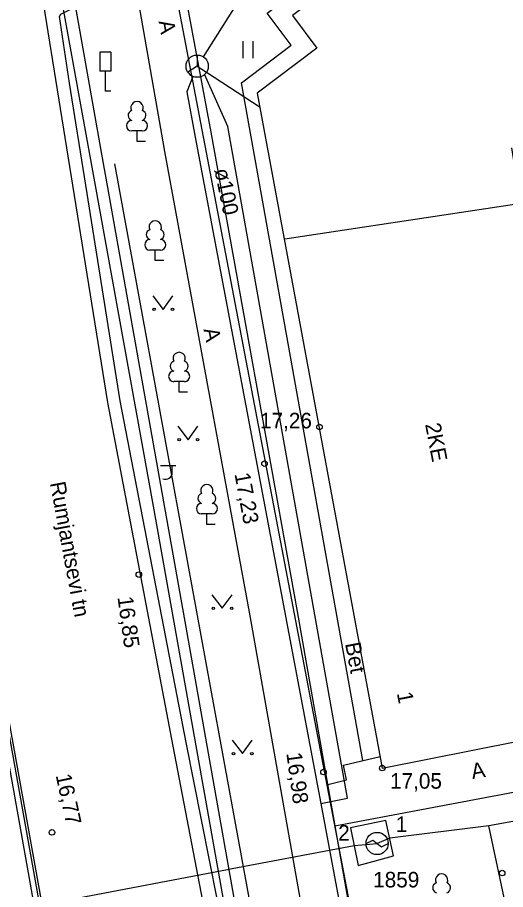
# Model space of a CAD drawing. Extents: x 713540 to 713867, y 6589774 to 6590061.
# Drawn here: x 713700.77 to 713722.79, y 6589841.34 to 6589880.65 of the extents above; entities that cross this region are included whole.
import ezdxf

# ---------------------------------------------------------------- set-up
doc = ezdxf.new("R2010")
doc.units = 0
for name, color, linetype in [('HALJASTUS', 7, 'Continuous'), ('HOONE', 7, 'Continuous'), ('HOONEDET', 7, 'Continuous'), ('KAEVU_NR', 7, 'Continuous'), ('KORGUS', 7, 'Continuous'), ('KPKAABEL', 7, 'Continuous'), ('LIIKLUS', 7, 'Continuous'), ('MPKAABEL', 7, 'Continuous'), ('PUU', 7, 'Continuous'), ('SIKAEV', 7, 'Continuous'), ('SITRASS', 7, 'Continuous'), ('TEE', 7, 'Continuous'), ('TORU NR', 7, 'Continuous'), ('По умолчанию', 7, 'Continuous'), ('Слой 1', 7, 'Continuous')]:
    doc.layers.add(name, color=color, linetype=linetype)

msp = doc.modelspace()

# ---------------------------------------------------------------- linework, layer by layer
at = {"layer": 'HALJASTUS'}
for p, q in [((713710.943, 6589879.583), (713710.943, 6589878.822)), ((713711.398, 6589879.583), (713711.398, 6589878.822)), ((713706.877, 6589868.097), (713707.34, 6589867.49)), ((713707.34, 6589867.49), (713707.786, 6589868.097)), ((713708.007, 6589862.227), (713708.47, 6589861.62)), ((713708.47, 6589861.62), (713708.916, 6589862.227)), ((713709.547, 6589854.627), (713710.01, 6589854.02)), ((713710.01, 6589854.02), (713710.456, 6589854.627)), ((713710.457, 6589848.077), (713710.92, 6589847.47)), ((713710.92, 6589847.47), (713711.366, 6589848.077))]:
    msp.add_line(p, q, dxfattribs=at)
msp.add_lwpolyline([(713705.159, 6589874.056), (713715.01, 6589820.21)], dxfattribs=at)
for centre, radius in [((713706.939, 6589867.49), 0.055), ((713707.768, 6589867.49), 0.055), ((713708.069, 6589861.62), 0.055), ((713708.898, 6589861.62), 0.055), ((713709.609, 6589854.02), 0.055), ((713710.438, 6589854.02), 0.055), ((713710.519, 6589847.47), 0.055), ((713711.348, 6589847.47), 0.055), ((713722.64, 6589842.085), 0.125)]:
    msp.add_circle(centre, radius, dxfattribs=at)
at = {"layer": 'HOONE'}
for p, q in [((713716.5, 6589843.42), (713716.8, 6589843.57)), ((713716.8, 6589843.57), (713717.2, 6589843.27)), ((713717.2, 6589843.27), (713717.5, 6589843.42))]:
    msp.add_line(p, q, dxfattribs=at)
for points in [[(713724.32, 6589875.59), (713727.08, 6589877.37), (713750.432, 6589865.811), (713755.151, 6589875.615), (713727.26, 6589889.056), (713724.566, 6589887.026), (713723.449, 6589888.508), (713713.179, 6589880.732), (713714.278, 6589879.273), (713711.586, 6589877.244), (713717.23, 6589846.82), (713727.46, 6589848.84), (713724.86, 6589863.5), (713723.07, 6589874.77)], [(713723.5, 6589872.27), (713712.84, 6589870.65)], [(713725.69, 6589844.87), (713722.04, 6589844.22)], [(713715.8, 6589844.12), (713716.15, 6589842.43), (713717.74, 6589842.87), (713717.39, 6589844.45), (713715.8, 6589844.12)], [(713722.04, 6589844.22), (713717.57, 6589843.66), (713717, 6589843.42)], [(713723.69, 6589836.46), (713722.04, 6589844.22)], [(713671.44, 6589834.87), (713687.15, 6589837.855), (713710.253, 6589842.245), (713710.463, 6589842.286), (713715.96, 6589843.33), (713717, 6589843.42)]]:
    msp.add_lwpolyline(points, dxfattribs=at)
msp.add_circle((713717, 6589843.42), 0.5, dxfattribs=at)
at = {"layer": 'HOONEDET'}
msp.add_lwpolyline([(713716.35, 6589847.16), (713710.876, 6589877.709), (713713.129, 6589879.407), (713712.044, 6589880.847), (713723.695, 6589889.578), (713724.782, 6589888.135), (713727.19, 6589889.95), (713755.786, 6589876.063), (713755.151, 6589875.615)], dxfattribs=at)
at = {"layer": 'KORGUS'}
for centre in [(713714.4, 6589862.19), (713711.92, 6589860.54), (713706.25, 6589855.54), (713714.58, 6589846.64), (713717.23, 6589846.82), (713702.33, 6589843.92)]:
    msp.add_circle(centre, 0.125, dxfattribs=at)
at = {"layer": 'KPKAABEL'}
for points in [[(713710.127, 6589839.185), (713708.399, 6589847.895), (713705.413, 6589863.377), (713703.858, 6589873.093), (713703.123, 6589877.685), (713702.671, 6589880.689), (713702.728, 6589880.803), (713706.087, 6589882.482), (713718.389, 6589891.098), (713722.849, 6589893.649), (713723.072, 6589893.73), (713723.275, 6589893.729), (713732.506, 6589888.949), (713748.351, 6589881.095), (713756.711, 6589877.059), (713763.861, 6589873.277), (713777.241, 6589866.985), (713783.126, 6589864.152), (713798.55, 6589856.631), (713806.554, 6589853.297)], [(713700.447, 6589886.145), (713701.061, 6589885.962), (713701.248, 6589885.623), (713703.334, 6589872.63), (713704.833, 6589863.294), (713707.784, 6589847.812), (713713.528, 6589817.88), (713715.336, 6589806.351), (713717.846, 6589793.663), (713718.024, 6589793.474), (713722.293, 6589793.794), (713723.951, 6589793.699), (713735.68, 6589793.289), (713735.884, 6589793.19), (713735.895, 6589792.126)]]:
    msp.add_lwpolyline(points, dxfattribs=at)
at = {"layer": 'LIIKLUS'}
for points in [[(713704.488, 6589879.085), (713704.488, 6589878.235)], [(713704.988, 6589879.085), (713704.488, 6589879.085)], [(713704.988, 6589879.085), (713704.988, 6589878.235)], [(713704.988, 6589878.235), (713704.488, 6589878.235)], [(713704.738, 6589878.235), (713704.738, 6589877.335)], [(713704.988, 6589877.335), (713704.738, 6589877.335)]]:
    msp.add_lwpolyline(points, dxfattribs=at)
at = {"layer": 'MPKAABEL'}
for points in [[(713694.011, 6589938.961), (713692.89, 6589933.64), (713698.13, 6589925.84), (713701.56, 6589922.83), (713707.37, 6589919), (713707.983, 6589913.318), (713708.27, 6589910.66), (713700.37, 6589905.55), (713699.23, 6589901.46), (713701.24, 6589889.8), (713704.212, 6589873.404), (713706.92, 6589858.46), (713712.25, 6589828.58), (713717.93, 6589797.45), (713721.28, 6589780.69), (713722.515, 6589774.068)], [(713733.391, 6589792.128), (713732.429, 6589795.958), (713729.329, 6589801.34), (713725.485, 6589806.569), (713715.308, 6589813.781), (713706.433, 6589812.173), (713706.056, 6589818.501), (713702.321, 6589837.617), (713696.514, 6589869.947), (713694.084, 6589874.558), (713687.448, 6589873.302), (713670.227, 6589869.773), (713666.658, 6589869.039)]]:
    msp.add_lwpolyline(points, dxfattribs=at)
at = {"layer": 'PUU'}
for p, q in [((713706.407, 6589875.535), (713705.927, 6589875.535)), ((713706.167, 6589875.06), (713706.167, 6589875.535)), ((713706.547, 6589875.06), (713706.167, 6589875.06)), ((713707.23, 6589870.165), (713706.75, 6589870.165)), ((713706.99, 6589869.69), (713706.99, 6589870.165)), ((713707.37, 6589869.69), (713706.99, 6589869.69)), ((713708.31, 6589864.235), (713707.83, 6589864.235)), ((713708.07, 6589863.76), (713708.07, 6589864.235)), ((713708.45, 6589863.76), (713708.07, 6589863.76)), ((713709.56, 6589858.275), (713709.08, 6589858.275)), ((713709.32, 6589857.8), (713709.32, 6589858.275)), ((713709.7, 6589857.8), (713709.32, 6589857.8))]:
    msp.add_line(p, q, dxfattribs=at)
for centre, radius, start, end in [((713706.167, 6589876.58), 0.277, 332.5799, 207.4201), ((713705.997, 6589876.232), 0.233, 109.0217, 253.1415), ((713706.337, 6589876.232), 0.233, 286.8508, 70.9859), ((713705.929, 6589875.772), 0.238, 90.0016, 269.3953), ((713706.404, 6589875.772), 0.238, 270.6047, 89.9984), ((713706.99, 6589871.21), 0.277, 332.5799, 207.4201), ((713706.82, 6589870.863), 0.233, 109.0217, 253.1415), ((713707.16, 6589870.863), 0.233, 286.8508, 70.9859), ((713706.753, 6589870.402), 0.238, 90.0016, 269.3953), ((713707.227, 6589870.402), 0.238, 270.6047, 89.9984), ((713708.07, 6589865.28), 0.277, 332.5799, 207.4201), ((713707.9, 6589864.933), 0.233, 109.0217, 253.1415), ((713708.24, 6589864.933), 0.233, 286.8508, 70.9859), ((713707.833, 6589864.472), 0.238, 90.0016, 269.3953), ((713708.307, 6589864.472), 0.238, 270.6047, 89.9984), ((713709.32, 6589859.32), 0.277, 332.5799, 207.4201), ((713709.15, 6589858.973), 0.233, 109.0217, 253.1415), ((713709.49, 6589858.973), 0.233, 286.8508, 70.9859), ((713709.083, 6589858.512), 0.238, 90.0016, 269.3953), ((713709.557, 6589858.512), 0.238, 270.6047, 89.9984), ((713719.91, 6589841.77), 0.277, 332.5799, 207.4201), ((713719.74, 6589841.423), 0.233, 109.0217, 253.1415), ((713720.08, 6589841.423), 0.233, 286.8508, 70.9859)]:
    msp.add_arc(centre, radius, start, end, dxfattribs=at)
at = {"layer": 'SIKAEV'}
for p, q in [((713708.882, 6589878.956), (713708.882, 6589878.456)), ((713708.882, 6589878.456), (713708.467, 6589878.181)), ((713708.882, 6589878.456), (713709.297, 6589878.181))]:
    msp.add_line(p, q, dxfattribs=at)
msp.add_circle((713708.882, 6589878.456), 0.5, dxfattribs=at)
at = {"layer": 'SITRASS'}
for points in [[(713722.087, 6589899.329), (713709.149, 6589878.879)], [(713714.46, 6589845.22), (713715.66, 6589845.46), (713710.263, 6589875.729), (713709.212, 6589878.088)], [(713709.301, 6589878.184), (713711.716, 6589876.611)], [(713708.693, 6589877.993), (713708.41, 6589877.3), (713708.797, 6589875.248), (713714.46, 6589845.22), (713715.85, 6589837.81), (713719.1, 6589820.87), (713720.22, 6589816.17)], [(713615.75, 6589870.91), (713621.3, 6589860.3), (713625.233, 6589860.869), (713625.227, 6589860.885), (713640.96, 6589863.23), (713652.708, 6589865.606), (713653.172, 6589865.67), (713666.653, 6589868.422), (713666.793, 6589868.454), (713693.51, 6589873.89), (713696.19, 6589872.18), (713705.63, 6589819.79), (713706.98, 6589814.25), (713714.585, 6589815.353), (713715.248, 6589815.449), (713720.22, 6589816.17), (713721.73, 6589808.13), (713722.95, 6589800.79), (713723.002, 6589800.484), (713723.148, 6589799.687), (713725.92, 6589783.295)]]:
    msp.add_lwpolyline(points, dxfattribs=at)
at = {"layer": 'TEE'}
for points in [[(713701.965, 6589889.306), (713702.632, 6589885.435), (713704.681, 6589873.818)], [(713707.387, 6589886.767), (713709.501, 6589875.479)], [(713705.687, 6589884.398), (713707.374, 6589874.782)], [(713709.501, 6589875.479), (713713.392, 6589853.877), (713718.226, 6589826.424), (713719.066, 6589821.759), (713719.238, 6589820.801), (713720.341, 6589814.674), (713720.518, 6589813.69), (713723.269, 6589798.406), (713724.259, 6589792.837)], [(713707.371, 6589874.781), (713711.263, 6589853.673), (713719.667, 6589806.269), (713718.326, 6589806.164), (713716.499, 6589807.387), (713708.381, 6589853.164), (713704.698, 6589873.833)], [(713706.743, 6589811.038), (713701.269, 6589842.093), (713695.587, 6589873.867)], [(713715.093, 6589844.217), (713727.941, 6589846.639), (713730.762, 6589846.637), (713743.437, 6589844.429), (713745.582, 6589842.842), (713746.953, 6589841.827), (713750.657, 6589839.086), (713750.506, 6589831.393), (713756.768, 6589831.776), (713753.813, 6589849.886), (713755.121, 6589855.667)], [(713714.718, 6589846.069), (713715.611, 6589846.293), (713715.48, 6589846.95), (713717.13, 6589847.34)]]:
    msp.add_lwpolyline(points, dxfattribs=at)
at = {"layer": 'По умолчанию'}
for p, q in [((713707.223, 6589860.46), (713707.92, 6589860.46)), ((713707.759, 6589860.139), (713707.759, 6589860.46))]:
    msp.add_line(p, q, dxfattribs=at)
msp.add_arc((713707.453, 6589860.139), 0.306, 246.3577, 0, dxfattribs=at)
at = {"layer": 'Слой 1'}
msp.add_lwpolyline([(713754.51, 6589852.01), (713745.66, 6589837.3), (713737.02, 6589835.72), (713729.39, 6589834.08), (713717.36, 6589832.34), (713707.43, 6589884.34), (713724.46, 6589897.32), (713765.74, 6589876.63)], close=True, dxfattribs=at)

# ---------------------------------------------------------------- texts
at = {"layer": 'HOONE'}
for s, p in [('2KE', (713719.161, 6589862.313)), ('1', (713717.887, 6589850.193))]:
    msp.add_text(s, height=0.7, rotation=280.8023, dxfattribs=at).set_placement(p)
at = {"layer": 'KAEVU_NR'}
msp.add_text('1859', height=0.7, dxfattribs=at).set_placement((713716.82, 6589841.44))
at = {"layer": 'KORGUS'}
for s, p in [('17,26', (713711.715, 6589862.13)), ('17,05', (713717.581, 6589845.89))]:
    msp.add_text(s, height=0.7, dxfattribs=at).set_placement(p)
for s, rotation, p in [('17,23', 280.4915, (713710.562, 6589860.074)), ('16,85', 277.7119, (713705.286, 6589854.52)), ('16,98', 277.7119, (713712.903, 6589847.49)), ('16,77', 282.1622, (713702.495, 6589846.49))]:
    msp.add_text(s, height=0.7, rotation=rotation, dxfattribs=at).set_placement(p)
at = {"layer": 'TEE'}
for s, rotation, p in [('A', 280.3401, (713707.138, 6589880.472)), ('A', 282.2826, (713709.16, 6589866.59)), ('Rumjantsevi tn', 280.4654, (713702.236, 6589859.667)), ('Bet', 280.722, (713715.55, 6589852.428)), ('A', 9.1936, (713721.3, 6589846.322))]:
    msp.add_text(s, height=0.7, rotation=rotation, dxfattribs=at).set_placement(p)
at = {"layer": 'TORU NR'}
msp.add_text('ø100', height=0.7, rotation=281.5922, dxfattribs=at).set_placement((713709.654, 6589873.781))
for s, p in [('1', (713717.838, 6589843.94)), ('2', (713715.244, 6589843.55))]:
    msp.add_text(s, height=0.7, dxfattribs=at).set_placement(p)

doc.saveas('drawing.dxf')
